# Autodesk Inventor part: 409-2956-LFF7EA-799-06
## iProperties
Created: 2010-11
Part Number: 409-2956-LFF7EA-799-06
Material: 3/4" OD TUBE - SS
Document SubType Name: Modeling
Designer: S. Boerckel
Engineer: Steve Boerckel
Mass: 340.704 g
Surface Area: 512.603 cm^2
Volume: 42.1664 cm^3
Density: 8.08 g/cm^3
Description: DRAIN TUBING
Length: 17.945 in
Author: S. Boerckel
Revision Number: 0
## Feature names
1. Sweep2
